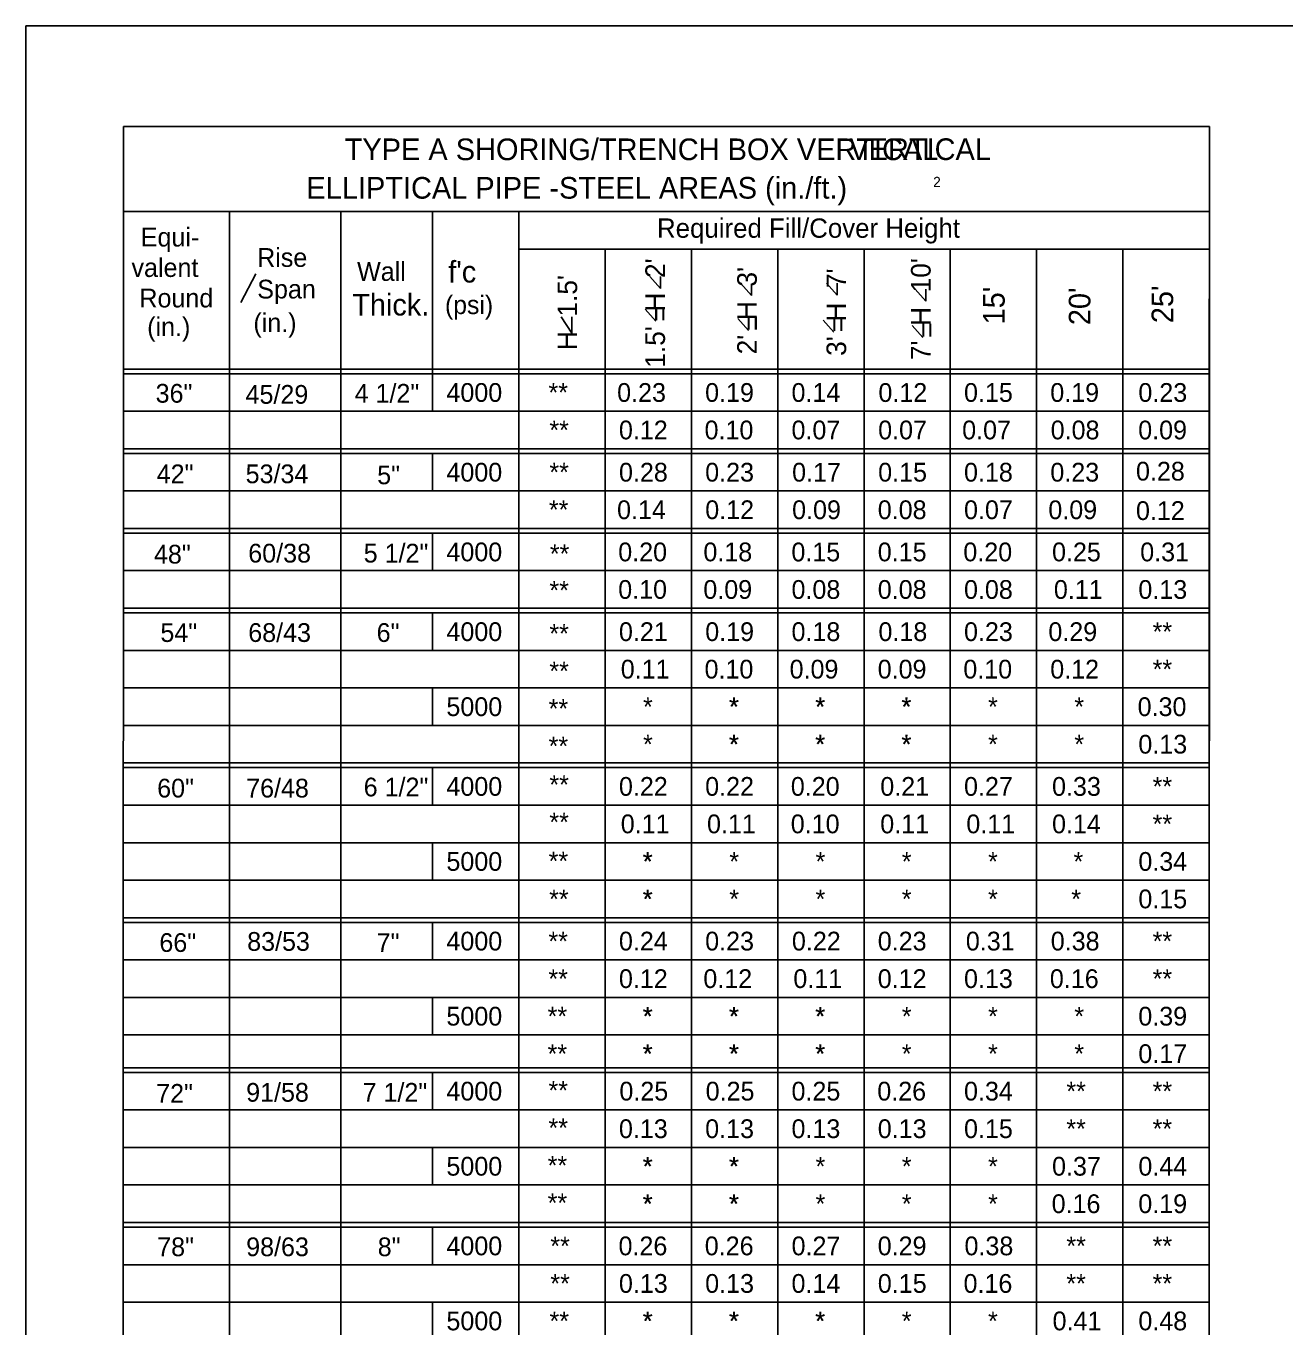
# Model space of a CAD drawing. Extents: x -22562 to -18409, y 3991 to 7171.
# Drawn here: x -19503.8 to -19319.2, y 6161.6 to 6352.4 of the extents above; entities that cross this region are included whole.
import ezdxf

# ---------------------------------------------------------------- set-up
doc = ezdxf.new("R2010")
doc.units = 0
for name, color, linetype in [('1', 7, 'Continuous'), ('2', 7, 'Continuous'), ('3', 7, 'Continuous'), ('4', 7, 'Continuous')]:
    doc.layers.add(name, color=color, linetype=linetype)

msp = doc.modelspace()

# ---------------------------------------------------------------- linework, layer by layer
at = {"layer": '1'}
for p, q in [((-19472.3, 6311.77), (-19470.1, 6316)), ((-19410.74, 6313.84), (-19412.3, 6315.61)), ((-19410.74, 6313.84), (-19410.74, 6315.59)), ((-19397.36, 6312.8), (-19398.93, 6314.56)), ((-19397.36, 6312.8), (-19397.36, 6314.55)), ((-19384.8, 6312.85), (-19386.36, 6314.62)), ((-19384.8, 6312.85), (-19384.8, 6314.61)), ((-19371.76, 6312), (-19373.32, 6313.77)), ((-19371.76, 6312), (-19371.76, 6313.76)), ((-19423.74, 6307.28), (-19425.3, 6309.7)), ((-19423.74, 6307.28), (-19423.74, 6309.69)), ((-19411.39, 6309.04), (-19412.96, 6310.8)), ((-19397.82, 6307.66), (-19399.38, 6309.43)), ((-19385.26, 6307.44), (-19386.82, 6309.21)), ((-19372.21, 6306.64), (-19373.77, 6308.41))]:
    msp.add_line(p, q, dxfattribs=at)
at = {"layer": '2'}
for p, q in [((-19503.85, 5788.37), (-19503.85, 6352.37)), ((-19503.85, 6352.37), (-18717.85, 6352.37)), ((-19489.54, 6337.62), (-19489.58, 6153.39)), ((-19489.54, 6337.62), (-19330.16, 6337.62)), ((-19330.16, 6337.62), (-19330.2, 6153.39)), ((-19489.58, 6325.15), (-19330.16, 6325.15)), ((-19474, 6325.15), (-19474, 6153.39)), ((-19457.62, 6325.15), (-19457.62, 6154.08)), ((-19444.16, 6325.15), (-19444.16, 6295.83)), ((-19431.5, 6325.15), (-19431.5, 6153.39)), ((-19431.5, 6319.64), (-19330.16, 6319.64)), ((-19418.83, 6319.64), (-19418.83, 6154.08)), ((-19406.17, 6319.64), (-19406.17, 6153.39)), ((-19393.51, 6319.64), (-19393.51, 6153.39)), ((-19380.85, 6319.64), (-19380.85, 6153.39)), ((-19368.19, 6319.64), (-19368.19, 6153.39)), ((-19355.52, 6319.64), (-19355.52, 6153.39)), ((-19342.86, 6319.64), (-19342.86, 6153.39)), ((-19330.2, 6312.35), (-19330.2, 6153.39)), ((-19489.58, 6302.02), (-19330.16, 6302.02)), ((-19489.58, 6301.34), (-19330.16, 6301.34)), ((-19457.62, 6301.34), (-19457.62, 6295.83)), ((-19444.16, 6301.34), (-19444.16, 6295.83)), ((-19489.58, 6295.83), (-19330.16, 6295.83)), ((-19489.58, 6290.33), (-19330.16, 6290.33)), ((-19489.58, 6290.33), (-19330.16, 6290.33)), ((-19489.58, 6289.64), (-19330.16, 6289.64)), ((-19457.62, 6289.64), (-19457.62, 6284.13)), ((-19444.16, 6289.64), (-19444.16, 6284.13)), ((-19489.58, 6284.13), (-19330.16, 6284.13)), ((-19489.58, 6278.63), (-19330.16, 6278.63)), ((-19489.58, 6278.63), (-19330.16, 6278.63)), ((-19489.58, 6277.94), (-19489.58, 6277.94)), ((-19489.58, 6277.94), (-19330.16, 6277.94)), ((-19457.62, 6277.94), (-19457.62, 6272.44)), ((-19444.16, 6277.94), (-19444.16, 6272.44)), ((-19489.58, 6272.44), (-19330.16, 6272.44)), ((-19489.58, 6266.93), (-19330.16, 6266.93)), ((-19489.58, 6266.93), (-19330.16, 6266.93)), ((-19489.58, 6266.24), (-19330.16, 6266.24)), ((-19457.62, 6266.24), (-19457.62, 6260.74)), ((-19444.16, 6266.24), (-19444.16, 6260.74)), ((-19489.58, 6260.74), (-19330.16, 6260.74)), ((-19489.58, 6255.23), (-19330.16, 6255.23)), ((-19457.62, 6255.23), (-19457.62, 6249.73)), ((-19444.16, 6255.23), (-19444.16, 6249.73)), ((-19489.58, 6249.73), (-19330.16, 6249.73)), ((-19489.58, 6244.22), (-19330.16, 6244.22)), ((-19489.58, 6244.22), (-19330.16, 6244.22)), ((-19489.58, 6243.53), (-19330.16, 6243.53)), ((-19457.62, 6243.54), (-19457.62, 6238.03)), ((-19444.16, 6243.54), (-19444.16, 6238.03)), ((-19489.58, 6238.03), (-19330.16, 6238.03)), ((-19489.58, 6232.52), (-19330.16, 6232.52)), ((-19457.62, 6232.52), (-19457.62, 6227.02)), ((-19444.16, 6232.52), (-19444.16, 6227.02)), ((-19489.58, 6227.02), (-19330.16, 6227.02)), ((-19489.58, 6221.51), (-19330.16, 6221.51)), ((-19489.58, 6221.51), (-19330.16, 6221.51)), ((-19489.58, 6220.83), (-19330.16, 6220.83)), ((-19457.62, 6220.83), (-19457.62, 6215.32)), ((-19444.16, 6220.83), (-19444.16, 6215.32)), ((-19489.58, 6215.32), (-19330.16, 6215.32)), ((-19489.58, 6209.82), (-19330.16, 6209.82)), ((-19457.62, 6209.82), (-19457.62, 6204.31)), ((-19444.16, 6209.82), (-19444.16, 6204.31)), ((-19489.58, 6204.31), (-19330.16, 6204.31)), ((-19489.58, 6199.49), (-19330.16, 6199.49)), ((-19489.58, 6198.81), (-19330.16, 6198.81)), ((-19489.58, 6198.81), (-19330.16, 6198.81)), ((-19457.62, 6198.81), (-19457.62, 6193.3)), ((-19444.16, 6198.81), (-19444.16, 6193.3)), ((-19489.58, 6193.3), (-19330.16, 6193.3)), ((-19489.58, 6187.8), (-19330.16, 6187.8)), ((-19457.62, 6187.8), (-19457.62, 6182.29)), ((-19444.16, 6187.8), (-19444.16, 6182.29)), ((-19489.58, 6182.29), (-19330.16, 6182.29)), ((-19489.58, 6176.79), (-19330.16, 6176.79)), ((-19489.58, 6176.79), (-19330.16, 6176.79)), ((-19489.58, 6176.1), (-19330.16, 6176.1)), ((-19457.62, 6176.1), (-19457.62, 6170.59)), ((-19444.16, 6176.1), (-19444.16, 6170.59)), ((-19489.58, 6170.59), (-19330.16, 6170.59)), ((-19489.58, 6165.09), (-19330.16, 6165.09)), ((-19457.62, 6165.09), (-19457.62, 6159.58)), ((-19444.16, 6165.09), (-19444.16, 6159.58))]:
    msp.add_line(p, q, dxfattribs=at)

# ---------------------------------------------------------------- texts
at = {"layer": '1'}
for s, height, p in [('VERTICAL', 3.178, (-19383, 6332.7)), ('Equi-', 2.751, (-19487, 6320.01)), ('Rise', 2.751, (-19469.92, 6317.02)), ('valent', 2.751, (-19488.36, 6315.54)), ('Wall', 2.751, (-19455.25, 6314.97)), ("f'c", 3.172, (-19441.87, 6314.72)), ('Span', 2.751, (-19469.9, 6312.38)), ('Round', 2.751, (-19487.2, 6311.07)), ('Thick.', 3.172, (-19455.97, 6309.88)), ('(psi)', 2.719, (-19442.35, 6310.09)), ('(in.)', 2.751, (-19486.06, 6306.86)), ('(in.)', 2.751, (-19470.47, 6307.45)), ('36"', 2.751, (-19484.82, 6297.09)), ('45/29', 2.751, (-19471.62, 6296.93)), ('4 1/2"', 2.751, (-19455.61, 6297.09)), ('42"', 2.751, (-19484.66, 6285.27)), ('53/34', 2.751, (-19471.61, 6285.27)), ('5"', 2.751, (-19452.3, 6285.12)), ('60/38', 2.751, (-19471.22, 6273.63)), ('5 1/2"', 2.751, (-19454.28, 6273.63)), ('48"', 2.751, (-19485.06, 6273.48)), ('54"', 2.751, (-19484.12, 6261.98)), ('68/43', 2.751, (-19471.22, 6261.98)), ('6"', 2.751, (-19452.38, 6261.98)), ('6 1/2"', 2.751, (-19454.28, 6239.31)), ('60"', 2.751, (-19484.59, 6239.15)), ('76/48', 2.751, (-19471.53, 6239.15)), ('66"', 2.751, (-19484.27, 6216.49)), ('83/53', 2.751, (-19471.38, 6216.65)), ('7"', 2.751, (-19452.38, 6216.49)), ('72"', 2.751, (-19484.74, 6194.35)), ('91/58', 2.751, (-19471.53, 6194.51)), ('7 1/2"', 2.751, (-19454.44, 6194.51)), ('78"', 2.751, (-19484.59, 6171.84)), ('98/63', 2.751, (-19471.53, 6171.84)), ('8"', 2.751, (-19452.22, 6171.84))]:
    msp.add_text(s, height=height, dxfattribs=at).set_placement(p)
for p in [(-19409.45, 6309.01), (-19395.87, 6307.63), (-19383.31, 6307.41), (-19370.26, 6306.61)]:
    msp.add_text('=', height=2.88, rotation=90, dxfattribs=at).set_placement(p)
at = {"layer": '2'}
for s, height, p in [('2', 1.5, (-19370.7, 6328.73)), ('Required Fill/Cover Height', 2.8357, (-19411.23, 6321.29))]:
    msp.add_text(s, height=height, dxfattribs=at).set_placement(p)
at = {"layer": '3'}
for s, height, rotation, p in [("15'", 3.172, 90, (-19360.2, 6308.58)), ("20'", 3.172, 90, (-19347.62, 6308.47)), ("25'", 3.172, 90, (-19335.47, 6308.76)), ('0.12', 2.751, 0.113, (-19378.73, 6297.2)), ('0.09', 2.751, 0.113, (-19340.6, 6291.7)), ('0.09', 2.751, 0.113, (-19353.79, 6279.99)), ('0.12', 2.751, 0.113, (-19340.93, 6279.87)), ('0.15', 2.751, 0.113, (-19391.5, 6273.8)), ('0.10', 2.751, 0.113, (-19416.92, 6268.3)), ('0.12', 2.751, 0.113, (-19353.51, 6256.6)), ('0.13', 2.753, 0.113, (-19340.58, 6245.59)), ('0.11', 2.751, 0.113, (-19378.46, 6233.89))]:
    msp.add_text(s, height=height, rotation=rotation, dxfattribs=at).set_placement(p)
for s, height, p in [('**', 2.753, (-19427.16, 6297.22)), ('0.23', 2.753, (-19417.08, 6297.21)), ('0.19', 2.753, (-19404.17, 6297.21)), ('0.14', 2.753, (-19391.49, 6297.21)), ('0.15', 2.753, (-19366.17, 6297.21)), ('0.19', 2.753, (-19353.51, 6297.21)), ('0.23', 2.753, (-19340.58, 6297.21)), ('**', 2.753, (-19427.03, 6291.71)), ('0.12', 2.753, (-19416.82, 6291.71)), ('0.10', 2.753, (-19404.25, 6291.71)), ('0.07', 2.753, (-19391.49, 6291.71)), ('0.07', 2.753, (-19378.77, 6291.71)), ('0.07', 2.753, (-19366.44, 6291.71)), ('0.08', 2.751, (-19353.45, 6291.71)), ('**', 2.753, (-19427.03, 6285.52)), ('0.28', 2.753, (-19416.81, 6285.51)), ('0.23', 2.753, (-19404.16, 6285.51)), ('0.17', 2.751, (-19391.4, 6285.51)), ('0.15', 2.753, (-19378.77, 6285.51)), ('0.18', 2.753, (-19366.17, 6285.51)), ('0.23', 2.753, (-19353.5, 6285.51)), ('0.28', 2.753, (-19340.93, 6285.66)), ('**', 2.753, (-19427.1, 6280.02)), ('0.14', 2.751, (-19417.09, 6280)), ('0.12', 2.753, (-19404.15, 6280)), ('0.09', 2.753, (-19391.4, 6280)), ('0.08', 2.753, (-19378.83, 6280)), ('0.07', 2.753, (-19366.17, 6280)), ('0.20', 2.753, (-19416.92, 6273.81)), ('0.18', 2.753, (-19404.42, 6273.81)), ('0.15', 2.753, (-19378.83, 6273.81)), ('0.20', 2.753, (-19366.27, 6273.81)), ('0.25', 2.753, (-19353.25, 6273.81)), ('0.31', 2.753, (-19340.31, 6273.81)), ('**', 2.753, (-19426.96, 6273.55)), ('**', 2.753, (-19427.03, 6268.19)), ('0.09', 2.753, (-19404.43, 6268.3)), ('0.08', 2.753, (-19391.49, 6268.3)), ('0.08', 2.753, (-19378.83, 6268.3)), ('0.08', 2.751, (-19366.17, 6268.3)), ('0.11', 2.753, (-19352.98, 6268.3)), ('0.13', 2.753, (-19340.58, 6268.3)), ('**', 2.753, (-19427.03, 6261.84)), ('0.21', 2.753, (-19416.82, 6262.11)), ('0.19', 2.753, (-19404.15, 6262.11)), ('0.18', 2.753, (-19391.49, 6262.11)), ('0.18', 2.753, (-19378.73, 6262.11)), ('0.23', 2.753, (-19366.17, 6262.11)), ('0.29', 2.753, (-19353.79, 6262.11)), ('**', 2.753, (-19338.49, 6262.11)), ('0.11', 2.753, (-19416.55, 6256.61)), ('0.10', 2.751, (-19404.25, 6256.61)), ('0.09', 2.753, (-19391.77, 6256.61)), ('0.09', 2.751, (-19378.84, 6256.61)), ('0.10', 2.751, (-19366.27, 6256.61)), ('**', 2.753, (-19338.49, 6256.61)), ('**', 2.753, (-19427.03, 6256.34)), ('*', 2.75, (-19413.28, 6251.1)), ('*', 2.75, (-19400.69, 6251.1)), ('*', 2.75, (-19400.62, 6251.1)), ('*', 2.75, (-19388.03, 6251.1)), ('*', 2.75, (-19387.96, 6251.1)), ('*', 2.75, (-19375.37, 6251.1)), ('*', 2.75, (-19375.3, 6251.1)), ('*', 2.75, (-19362.64, 6251.1)), ('*', 2.75, (-19349.98, 6251.1)), ('0.30', 2.753, (-19340.69, 6251.1)), ('**', 2.753, (-19427.14, 6250.83)), ('**', 2.753, (-19427.14, 6245.33)), ('*', 2.75, (-19413.28, 6245.6)), ('*', 2.75, (-19400.69, 6245.6)), ('*', 2.75, (-19400.62, 6245.6)), ('*', 2.75, (-19388.03, 6245.6)), ('*', 2.75, (-19387.96, 6245.6)), ('*', 2.75, (-19375.37, 6245.6)), ('*', 2.75, (-19375.3, 6245.6)), ('*', 2.75, (-19362.64, 6245.6)), ('*', 2.75, (-19349.98, 6245.6)), ('**', 2.753, (-19427.03, 6239.67)), ('0.22', 2.753, (-19416.82, 6239.4)), ('0.22', 2.753, (-19404.16, 6239.4)), ('0.20', 2.753, (-19391.59, 6239.4)), ('0.21', 2.753, (-19378.46, 6239.4)), ('0.27', 2.753, (-19366.17, 6239.4)), ('0.33', 2.753, (-19353.25, 6239.4)), ('**', 2.753, (-19338.49, 6239.4)), ('**', 2.753, (-19427.03, 6234.17)), ('0.11', 2.753, (-19416.55, 6233.9)), ('0.11', 2.753, (-19403.89, 6233.9)), ('0.10', 2.753, (-19391.6, 6233.9)), ('0.11', 2.753, (-19365.83, 6233.9)), ('0.14', 2.753, (-19353.25, 6233.9)), ('**', 2.753, (-19338.49, 6233.9)), ('**', 2.753, (-19427.14, 6228.46)), ('*', 2.75, (-19413.35, 6228.39)), ('*', 2.75, (-19413.28, 6228.39)), ('*', 2.75, (-19400.62, 6228.39)), ('*', 2.75, (-19387.96, 6228.39)), ('*', 2.75, (-19375.3, 6228.39)), ('*', 2.75, (-19362.64, 6228.39)), ('*', 2.75, (-19350.1, 6228.39)), ('0.34', 2.753, (-19340.58, 6228.39)), ('**', 2.753, (-19427.07, 6222.88)), ('*', 2.75, (-19413.35, 6222.89)), ('*', 2.75, (-19413.28, 6222.89)), ('*', 2.75, (-19400.62, 6222.89)), ('*', 2.75, (-19387.96, 6222.89)), ('*', 2.75, (-19375.3, 6222.89)), ('*', 2.75, (-19362.64, 6222.89)), ('*', 2.75, (-19350.43, 6222.89)), ('0.15', 2.753, (-19340.58, 6222.89)), ('**', 2.753, (-19427.17, 6216.69)), ('0.24', 2.753, (-19416.82, 6216.7)), ('0.23', 2.753, (-19404.16, 6216.7)), ('0.22', 2.753, (-19391.43, 6216.7)), ('0.23', 2.753, (-19378.83, 6216.7)), ('0.31', 2.753, (-19365.9, 6216.7)), ('0.38', 2.753, (-19353.44, 6216.7)), ('**', 2.753, (-19338.49, 6216.7)), ('**', 2.753, (-19427.17, 6211.18)), ('0.12', 2.753, (-19416.82, 6211.19)), ('0.12', 2.753, (-19404.43, 6211.19)), ('0.11', 2.753, (-19391.22, 6211.19)), ('0.12', 2.753, (-19378.83, 6211.19)), ('0.13', 2.753, (-19366.17, 6211.19)), ('0.16', 2.753, (-19353.57, 6211.19)), ('**', 2.753, (-19338.49, 6211.19)), ('**', 2.753, (-19427.29, 6205.68)), ('*', 2.75, (-19413.35, 6205.68)), ('*', 2.75, (-19413.28, 6205.68)), ('*', 2.75, (-19400.69, 6205.68)), ('*', 2.75, (-19400.62, 6205.68)), ('*', 2.75, (-19388.03, 6205.68)), ('*', 2.75, (-19387.96, 6205.68)), ('*', 2.75, (-19375.3, 6205.68)), ('*', 2.75, (-19362.64, 6205.68)), ('*', 2.75, (-19349.98, 6205.68)), ('0.39', 2.753, (-19340.59, 6205.68)), ('**', 2.753, (-19427.29, 6200.17)), ('*', 2.75, (-19413.35, 6200.18)), ('*', 2.75, (-19413.28, 6200.18)), ('*', 2.75, (-19400.69, 6200.18)), ('*', 2.75, (-19400.62, 6200.18)), ('*', 2.75, (-19388.03, 6200.18)), ('*', 2.75, (-19387.96, 6200.18)), ('*', 2.75, (-19375.3, 6200.18)), ('*', 2.75, (-19362.64, 6200.18)), ('*', 2.75, (-19349.98, 6200.18)), ('0.17', 2.753, (-19340.58, 6200.18)), ('**', 2.753, (-19427.16, 6194.8)), ('0.25', 2.753, (-19416.75, 6194.68)), ('0.25', 2.753, (-19404.09, 6194.68)), ('0.25', 2.753, (-19391.49, 6194.68)), ('0.26', 2.753, (-19378.9, 6194.68)), ('0.34', 2.753, (-19366.17, 6194.68)), ('**', 2.753, (-19351.15, 6194.68)), ('**', 2.753, (-19338.49, 6194.68)), ('**', 2.753, (-19427.16, 6189.3)), ('0.13', 2.753, (-19416.82, 6189.17)), ('0.13', 2.753, (-19404.16, 6189.17)), ('0.13', 2.753, (-19391.49, 6189.17)), ('0.13', 2.753, (-19378.83, 6189.17)), ('0.15', 2.753, (-19366.17, 6189.17)), ('**', 2.753, (-19351.15, 6189.17)), ('**', 2.753, (-19338.49, 6189.17)), ('**', 2.753, (-19427.28, 6183.79)), ('*', 2.75, (-19413.35, 6183.66)), ('*', 2.75, (-19413.28, 6183.66)), ('*', 2.75, (-19400.69, 6183.66)), ('*', 2.75, (-19400.62, 6183.66)), ('*', 2.75, (-19387.96, 6183.66)), ('*', 2.75, (-19375.3, 6183.66)), ('*', 2.75, (-19362.64, 6183.66)), ('0.37', 2.753, (-19353.25, 6183.66)), ('0.44', 2.753, (-19340.58, 6183.66)), ('**', 2.753, (-19427.28, 6178.29)), ('*', 2.75, (-19413.35, 6178.16)), ('*', 2.75, (-19413.28, 6178.16)), ('*', 2.75, (-19400.69, 6178.16)), ('*', 2.75, (-19400.62, 6178.16)), ('*', 2.75, (-19387.96, 6178.16)), ('*', 2.75, (-19375.3, 6178.16)), ('*', 2.75, (-19362.64, 6178.16)), ('0.16', 2.753, (-19353.31, 6178.16)), ('0.19', 2.753, (-19340.59, 6178.16)), ('**', 2.753, (-19426.89, 6171.96)), ('0.26', 2.753, (-19416.88, 6171.97)), ('0.26', 2.753, (-19404.22, 6171.97)), ('0.27', 2.753, (-19391.48, 6171.97)), ('0.29', 2.753, (-19378.84, 6171.97)), ('0.38', 2.753, (-19366.1, 6171.97)), ('**', 2.753, (-19351.15, 6171.97)), ('**', 2.753, (-19338.49, 6171.97)), ('**', 2.753, (-19426.89, 6166.46)), ('0.13', 2.753, (-19416.82, 6166.46)), ('0.13', 2.753, (-19404.16, 6166.46)), ('0.14', 2.753, (-19391.49, 6166.46)), ('0.15', 2.753, (-19378.82, 6166.46)), ('0.16', 2.753, (-19366.24, 6166.46)), ('**', 2.753, (-19351.15, 6166.46)), ('**', 2.753, (-19338.49, 6166.46)), ('**', 2.753, (-19427.01, 6160.96)), ('*', 2.75, (-19413.35, 6160.96)), ('*', 2.75, (-19413.28, 6160.96)), ('*', 2.75, (-19400.69, 6160.96)), ('*', 2.75, (-19400.62, 6160.96)), ('*', 2.75, (-19388.03, 6160.96)), ('*', 2.75, (-19387.96, 6160.96)), ('*', 2.75, (-19375.3, 6160.96)), ('*', 2.75, (-19362.64, 6160.96)), ('0.41', 2.753, (-19353.17, 6160.96)), ('0.48', 2.753, (-19340.58, 6160.96))]:
    msp.add_text(s, height=height, dxfattribs=at).set_placement(p)
at = {"layer": '4'}
for s, height, p in [('TYPE A SHORING/TRENCH BOX VERTICAL', 3.1784, (-19457.07, 6332.68)), ('ELLIPTICAL PIPE -STEEL AREAS (in./ft.)', 3.1784, (-19462.69, 6327.03)), ('4000', 2.753, (-19442.14, 6297.21)), ('4000', 2.753, (-19442.14, 6285.51)), ('4000', 2.753, (-19442.14, 6273.81)), ('4000', 2.753, (-19442.14, 6262.11)), ('5000', 2.753, (-19442.14, 6251.1)), ('4000', 2.753, (-19442.14, 6239.4)), ('5000', 2.753, (-19442.14, 6228.39)), ('4000', 2.753, (-19442.14, 6216.7)), ('5000', 2.753, (-19442.14, 6205.68)), ('4000', 2.753, (-19442.14, 6194.68)), ('5000', 2.753, (-19442.14, 6183.66)), ('4000', 2.753, (-19442.14, 6171.97)), ('5000', 2.753, (-19442.14, 6160.96))]:
    msp.add_text(s, height=height, dxfattribs=at).set_placement(p)
for s, height, p in [("1.5'  H  2'", 2.8834, (-19410.06, 6302.22)), ("2'  H  3'", 2.883, (-19396.58, 6304.18)), ("3'  H  7'", 2.883, (-19383.47, 6303.96)), ("7'  H  10'", 2.883, (-19371.07, 6303.33)), ("H  1.5'", 2.883, (-19422.95, 6304.8))]:
    msp.add_text(s, height=height, rotation=90, dxfattribs=at).set_placement(p)

doc.saveas('drawing.dxf')
